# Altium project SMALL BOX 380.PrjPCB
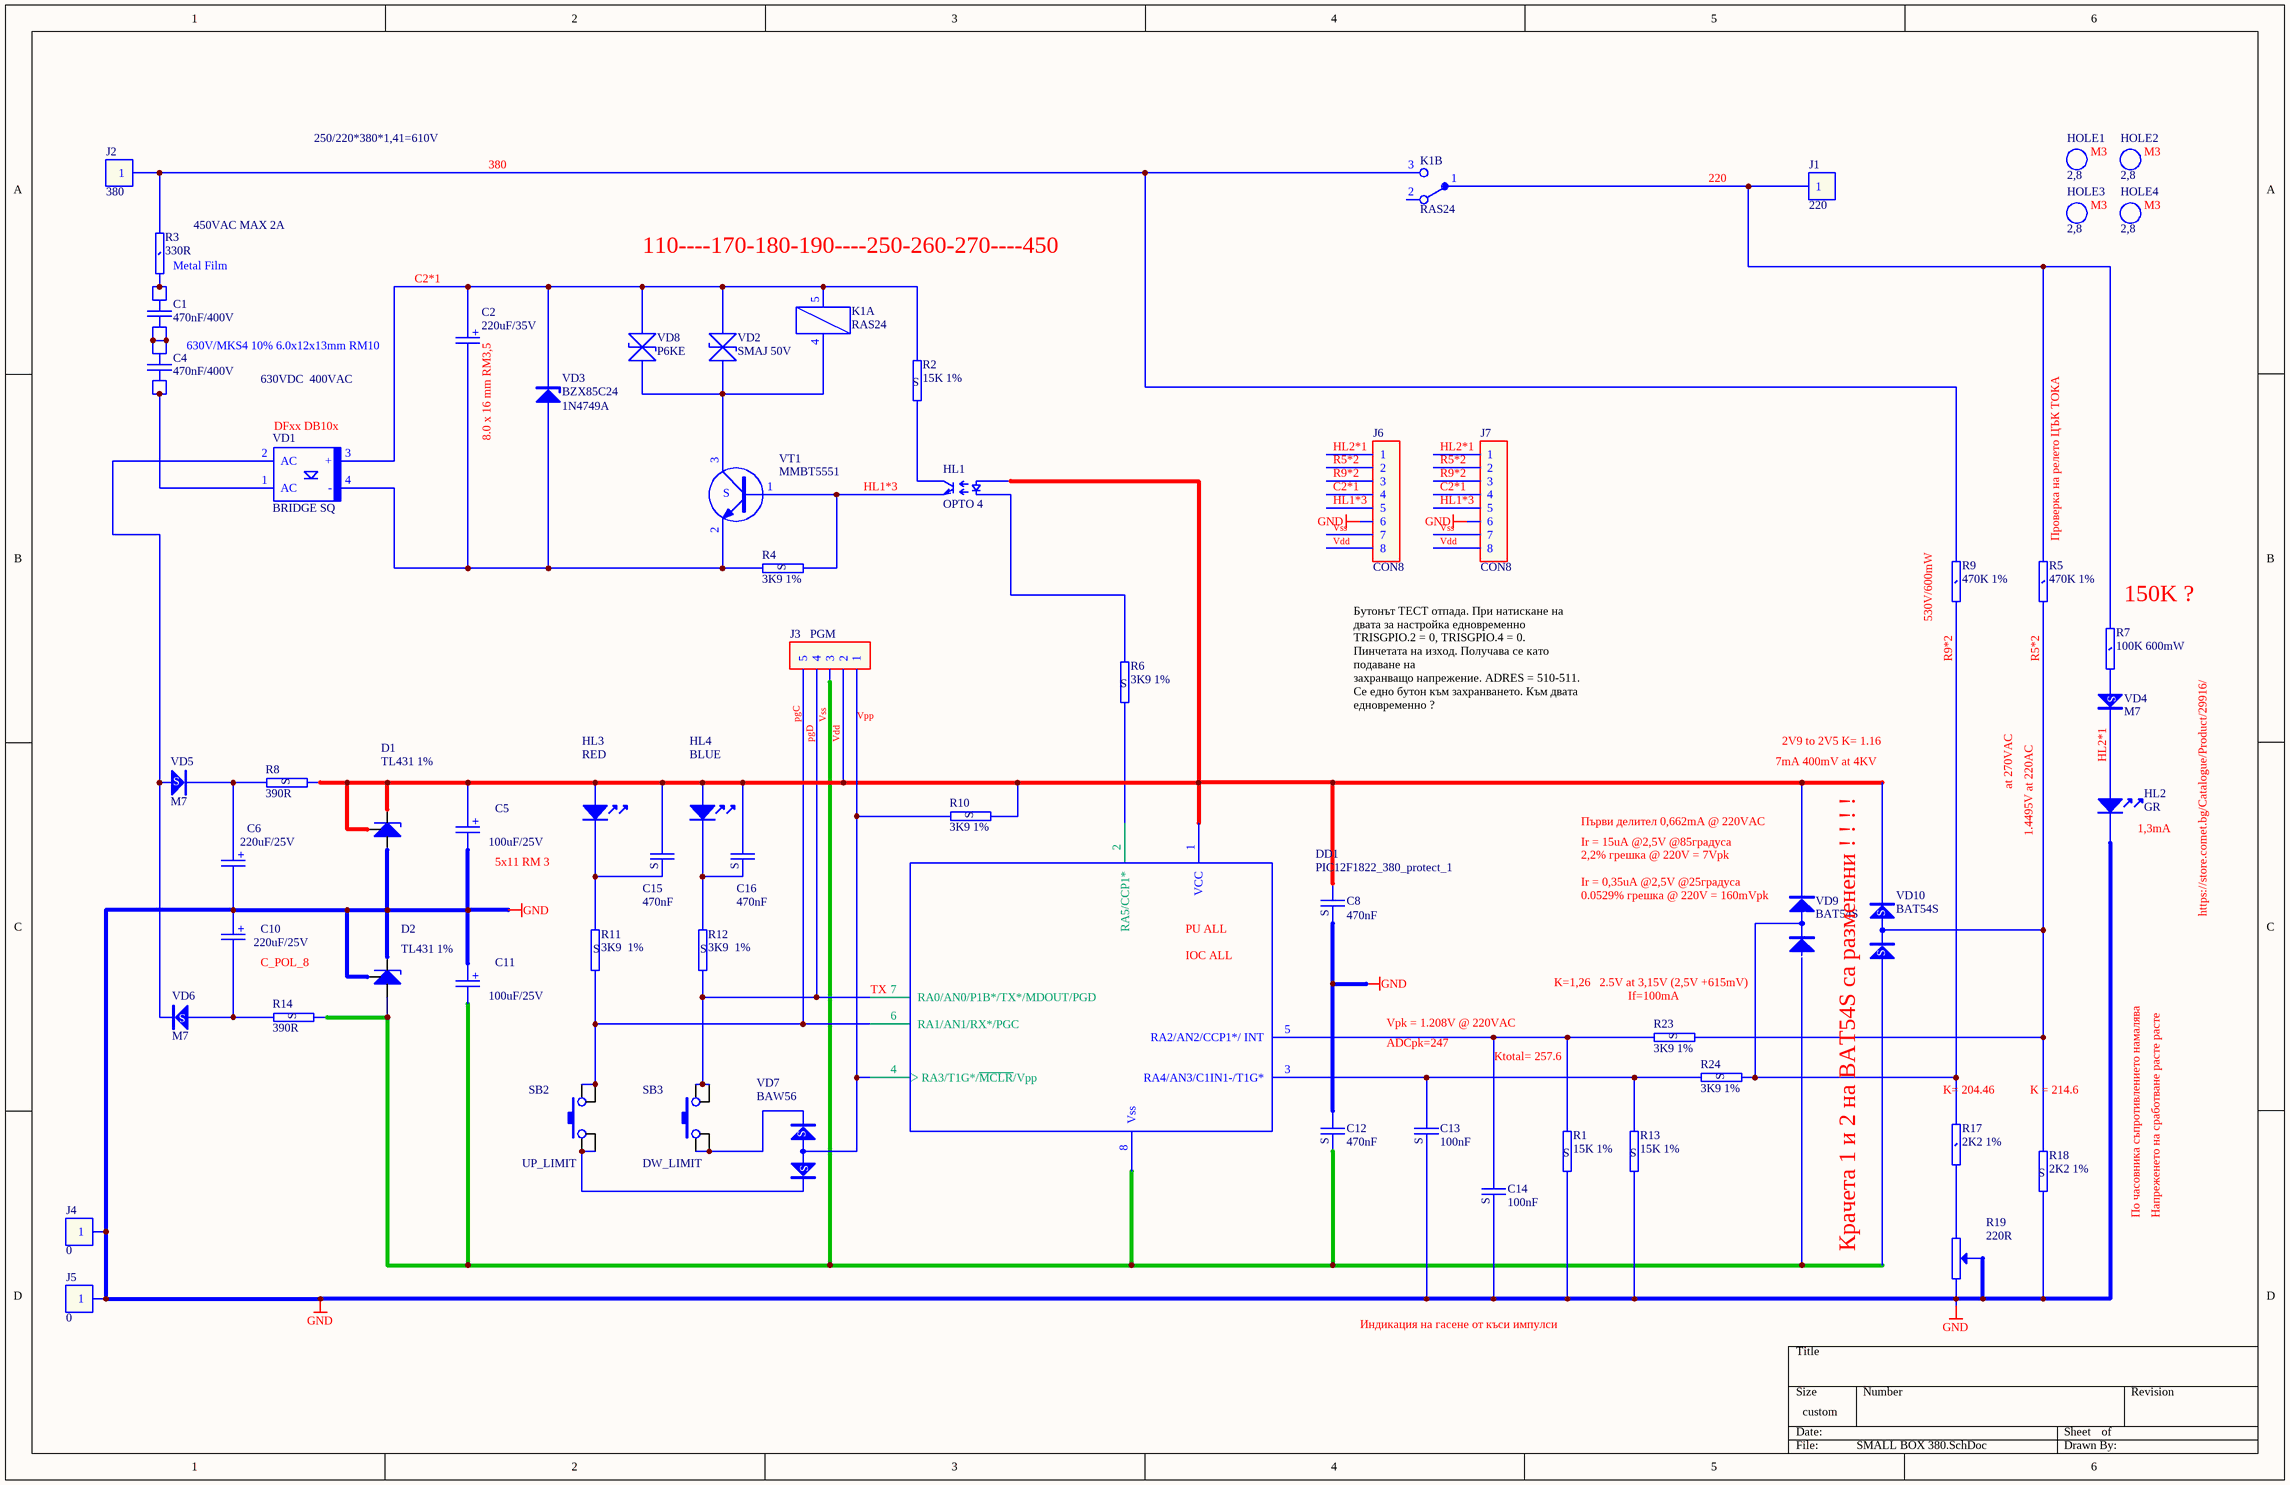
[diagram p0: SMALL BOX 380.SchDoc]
1 sheet, 64 parts. Net scope: global (net labels, ports and power ports of the same name join across sheets).
Board file: SMALL BOX 380.PcbDoc

## Sheet SMALL BOX 380.SchDoc
size 431 x 279 mm; PageSetup: Record=PageOptions|CenterHorizontal=True|CenterVertical=True|PrintScale=0.64|XCorrection=1.00|YCorrection=1.00|PrintKind=0|BorderSize=5000000|LeftOffset=0|BottomOffset=0|Orientation=2|PaperLength=1000|PaperWidth=1000|Scale=100|PaperSource=15|PrintQuality=600|MediaType=1|DitherType=10|PaperKind=Letter|PrintScaleMode=1

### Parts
C1  470nF/400V  [C RM15+22,5]
C2  220uF/35V  [C_POL9X4]
C4  470nF/400V  [C RM15+22,5]
C5  100uF/25V  [C_POL_6]
C6  220uF/25V  [C_POL_8]
C8  470nF  [0805_STS]
C10  220uF/25V  [C_POL_8]
C11  100uF/25V  [C_POL_6]
C12  470nF  [0805_STS]
C13  100nF  [0805_STS]
C14  100nF  [0805_STS]
C15  470nF  [0805_STS]
C16  470nF  [0805_STS]
D1  TL431 1%  [SOT-23]
D2  TL431 1%  [SOT-23]
DD1  PIC12F1822_380_protect_1  [SO-8]
HL1  OPTO 4  [DIP4]
HL2  GR  [LED3]
HL3  RED  [LED3]
HL4  BLUE  [LED3]
HOLE1  2,8  [HOLE2,8]
HOLE2  2,8  [HOLE2,8]
HOLE3  2,8  [HOLE2,8]
HOLE4  2,8  [HOLE2,8]
J1  220  [PAD2,2]
J2  380  [PAD2,2]
J3  PGM  [SIP5]
J4  0  [PAD2,2]
J5  0  [PAD2,2]
J6  CON8  [SIP8]
J7  CON8  [SIP8]
K1  RAS24  [UNI 10A]  (parts A,B of 2)
R1  15K 1%  [0805_STS]
R2  15K 1%  [0805_STS]
R3  330R  [R1/4]
R4  3K9 1%  [0805_STS]
R5  470K 1%  [R1/4]
R6  3K9 1%  [0805_STS]
R7  100K 600mW  [R1/4]
R8  390R  [1206_STS]
R9  470K 1%  [R1/4]
R10  3K9 1%  [0805_STS]
R11  3K9  1%  [0805_STS]
R12  3K9  1%  [0805_STS]
R13  15K 1%  [0805_STS]
R14  390R  [1206_STS]
R17  2K2 1%  [0805_STS]
R18  2K2 1%  [0805_STS]
R19  220R  [RT_7.5X5_2]
R23  3K9 1%  [0805_STS]
R24  3K9 1%  [0805_STS]
SB2  UP_LIMIT  [BTN BIG OMRON B3F]
SB3  DW_LIMIT  [BTN BIG OMRON B3F]
VD1  BRIDGE SQ  [BRIDGE SQ TH]
VD2  SMAJ 50V  [SMB]
VD3  BZX85C24  [1N4004]
VD4  M7  [SMA]
VD5  M7  [SMA]
VD6  M7  [SMA]
VD7  BAW56  [SOT-23-STS]
VD8  P6KE  [1N4004]
VD9  BAT54S  [SOT-23-STS]
VD10  BAT54S  [SOT-23-STS]
VT1  MMBT5551  [SOT-23-STS]

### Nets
GND: C5.2 C6.2 C8.2 C10.1 C11.1 C12.1 C13.2 C14.2 D1.3(GND) D2.1(VIN) D2.2(VZ) HL2.2 J4.1 J5.1 J6.6 J7.6 R1.1 R13.1 R18.1 R19.2 R19.3
220: J1.1 K1.1 R5.1 R7.1
380: J2.1 K1.3 R3.1 R9.1
C2*1: C2.1 J6.4 J7.4 K1.5 R2.2 VD1.3(+) VD2.1 VD3.2 VD8.2
HL1*3: HL1.3 J6.5 J7.5 R4.2 VT1.1
HL2*1: HL2.1 J6.1 J7.1 VD4.2
pgC: DD1.6(RA1/AN1/RX*/PGC) J3.5 R11.2 SB2.2 SB2.2'
pgD: DD1.7(RA0/AN0/P1B*/TX*/MDOUT/PGD) J3.4 R12.2 SB3.2 SB3.2'
R5*2: J6.2 J7.2 R5.2 R18.2 R23.2 VD10.3
R9*2: J6.3 J7.3 R9.2 R17.1 R24.2 VD9.3
Vdd: C5.1 C8.1 C15.1 C16.1 D1.1(VIN) D1.2(VZ) DD1.1(VCC) HL1.1 HL3.1 HL4.1 J3.2 J6.8 J7.8 R8.2 R10.2 VD9.1 VD10.1
Vpp: DD1.4(RA3/T1G*/~{MCLR}/Vpp) J3.1 R10.1 VD7.3
Vss: C11.2 C12.2 D2.3(GND) DD1.8(Vss) J3.3 J6.7 J7.7 R14.2 VD9.2 VD10.2
NetC1_1: C1.1 C1.1' R3.2
NetC1_2: C1.2 C1.2' C4.1 C4.1'
NetC2_2: C2.2 R4.1 VD1.4(-) VD3.1 VT1.2
NetC4_2: C4.2 C4.2' VD1.1(AC)
NetC6_1: C6.1 R8.1 VD5.2
NetC10_2: C10.2 R14.1 VD6.1
NetC13_1: C13.1 DD1.3(RA4/AN3/C1IN1-/T1G*) R13.2 R24.1
NetC14_1: C14.1 DD1.5(RA2/AN2/CCP1*/_INT) R1.2 R23.1
NetC15_2: C15.2 HL3.2 R11.1
NetC16_2: C16.2 HL4.2 R12.1
NetDD1_2: DD1.2(RA5/CCP1*) R6.1
NetHL1_2: HL1.2 R6.2
NetHL1_4: HL1.4 R2.1
NetK1_4: K1.4 VD2.2 VD8.1 VT1.3
NetR7_2: R7.2 VD4.1
NetR17_2: R17.2 R19.1
NetSB2_1: SB2.1 SB2.1' VD7.2
NetSB3_1: SB3.1 SB3.1' VD7.1
NetVD1_2: VD1.2(AC) VD5.1 VD6.2

Not connected (* = marked no-connect by the designer): K1 2

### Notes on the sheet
- 250/220*380*1,41=610V
- (near R3) 450VAC MAX 2A
- (near R3) Metal Film
- 110----170-180-190----250-260-270----450
- 630V/MKS4 10% 6.0x12x13mm RM10
- 630VDC  400VAC
- (near VD1) DFxx DB10x
- (near C2) 8.0 x 16 mm RM3,5
- (near VD3) 1N4749A
- (near R5) Проверка на релето ЦЪК ТОКА
- (near R9) 530V/600mW
- (near R7) 150K ?
- Бутонът ТЕСТ отпада. При натискане на двата за настройка едновременно
  TRISGPIO.2 = 0, TRISGPIO.4 = 0. Пинчетата на изход. Получава се като подаване на
  захранващо напрежение. ADRES = 510-511. Се едно бутон към захранването. Към двата едновременно ?
- 7mA 400mV at 4KV
- 2V9 to 2V5 K= 1.16
- Първи делител 0,662mA @ 220VAC
- at 270VAC
- 1.4495V at 220AC
- (near HL2) 1,3mA
- 5x11 RM 3
- Ir = 15uA @2,5V @85градуса
- 2,2% грешка @ 220V = 7Vpk
- (near VD9) Ir = 0,35uA @2,5V @25градуса
- (near VD9) 0.0529% грешка @ 220V = 160mVpk
- C_POL_8
- https://store.comet.bg/Catalogue/Product/29916/
- (near DD1) TX
- Vpk = 1.208V @ 220VAC
- K=1,26   2.5V at 3,15V (2,5V +615mV)
- (near R23) If=100mA
- ADCpk=247
- Ktotal= 257.6
- (near R17) K= 204.46
- K = 214.6
- По часовника съпротивлението намалява
- Напреженето на сработване расте расте
- Крачета 1 и 2 на BAT54S са разменени ! ! ! !
- Индикация на гасене от къси импулси

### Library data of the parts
C1 C4 = C RM15+22,5
C2 C5 C6 C10 C11 = C-POL
C8 C12-C16 = C-SMD
D1 D2 = D_ZR431: Reference Zener Diode; Manufacturer: Diodes Inc.; Value/Type: ZR431
HL2-HL4 = LED
HOLE1-HOLE4 = HOLE
J1 J2 J4 J5 = CON1
J3 = CON5
K1 = RELAY 1GR
R1 R2 R4 R6 R8 R10-R14 R18 R23 R24 = R-SMD
R3 R5 R7 R9 R17 = R1/4
R19 = R-TRIM
SB2 SB3 = SW-BUTTON A
VD2 VD8 = SIBAR
VD3 = DIODE ZENER
VD4-VD6 = DIODE-SMD
VD7 = DIODE-CA
VD9 VD10 = DIODE-DBL
VT1 = NPN-SMD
